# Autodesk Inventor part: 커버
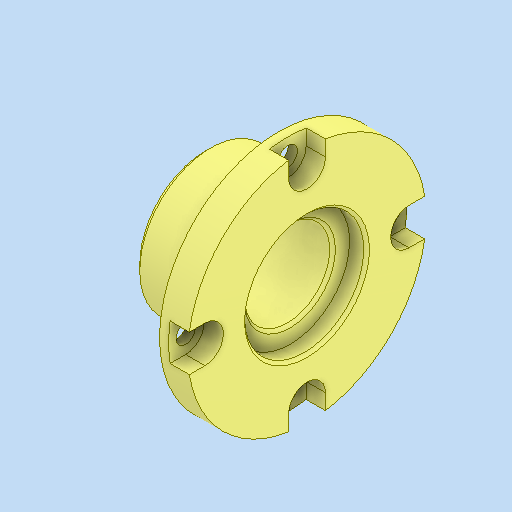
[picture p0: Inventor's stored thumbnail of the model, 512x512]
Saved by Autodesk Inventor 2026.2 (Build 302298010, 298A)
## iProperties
Created: 2026-08
Part Number: 커버
Material: 알루미늄 6061
Document SubType Name: Modeling
Designer: PC2-02
Density: 2.71 g/cm^3
Appearance: 기본값
Author: jhkim
Sending System: Autodesk Inventor 2027
Preprocessor: ST-DEVELOPER v20.1
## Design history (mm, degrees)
feature "솔리드1"
node "솔리드2"
